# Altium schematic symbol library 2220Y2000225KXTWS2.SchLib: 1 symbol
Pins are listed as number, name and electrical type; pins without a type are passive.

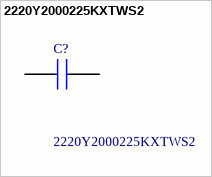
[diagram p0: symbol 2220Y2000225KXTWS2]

## 2220Y2000225KXTWS2
designator C?
Multilayer Ceramic Capacitors MLCC - SMD/SMT 2.2UF   200V   10%        2220; Manufacturer_Name: Knowles; Geometry.Height: 4.5mm
footprint CAPC5750X450N
pins: 1, 2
